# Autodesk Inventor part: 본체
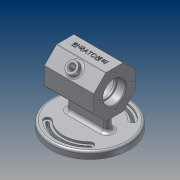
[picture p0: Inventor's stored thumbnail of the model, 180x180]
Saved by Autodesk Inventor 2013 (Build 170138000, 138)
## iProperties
Created: 2017-06
Part Number: 본체
Material: 알루미늄 6061
Document SubType Name: Modeling
Designer: Windows7
Density: 2.71 g/cm^3
Mass: 562.523 g
Surface Area: 565.555 cm^2
Volume: 207.573 cm^3
Author: Windows7
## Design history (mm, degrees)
sketch "스케치1" dims "d0" = 60
  geometry: L1 (12.426, 30)-(30, 12.426); L2 (30, 12.426)-(30, -12.426); L3 (30, -12.426)-(12.426, -30); L4 (12.426, -30)-(-12.426, -30); L5 (-12.426, -30)-(-30, -12.426); L6 (-30, -12.426)-(-30, 12.426); L7 (-30, 12.426)-(-12.426, 30); L8 (-12.426, 30)-(12.426, 30); 4 further points
  constraints: 16 end point, 2 coincident, 2 vertical alignment, 1 midpoint, 19 other
extrude "돌출1" new body sketch "스케치1" stored distance "d1" = 70; taper "d2" = 0 deg
sketch "스케치2"
  geometry: C1 r 25 at (0, 0); 1 further point
  constraints: 1 centre point, 1 coincident
  dimensions: "d3" = 50 diameter of C1
extrude "돌출2" cut sketch "스케치2" stored distance "d4" = 40; taper "d5" = 0 deg
sketch "스케치3"
  geometry: 1 further point
hole "구멍1" sketch "스케치3" at (0, 0) diameter "d6" = 28; stored, may be unused: countersink angle "d10" = 90 deg, drill point angle "d12" = 0 deg; dims "d7" = 6, "d8" = 32, "d9" = 12, "d11" = 15
chamfer "모따기1" distance "d13" = 1; stored, may be unused: second distance "d14" = 2, angle "d15" = 45 deg
node "작업 평면1"
sketch "스케치4"
  geometry: C1 r 55 at (0, 0); 1 further point
  constraints: 1 centre point, 1 coincident
  dimensions: "d17" = 110 diameter of C1
extrude "돌출3" join sketch "스케치4" distance "d18" = 10; taper "d19" = 0 deg
sketch "스케치5" dims "d20" = 86
  geometry: L1 (0, 55)-(0, -55); L2 (0, 0)-(-38.891, 38.891); A1 r 55 centre (0, 0) between (0, 55) and (0, -55) reference; A2 r 48 centre (0, 0) between (33.941, 33.941) and (-33.941, 33.941); A3 r 38 centre (0, 0) between (26.87, 26.87) and (-26.87, 26.87); A4 r 5 centre (-30.406, 30.406) between (-33.941, 33.941) and (-26.87, 26.87); A5 r 5 centre (30.406, 30.406) between (26.87, 26.87) and (33.941, 33.941)
  constraints: 11 point on circle, 4 centre point, 4 end point, 2 coincident, 1 midpoint, 1 point on line, 1 symmetric about line, 1 tangent, 1 vertical, 4 other
  dimensions: "d21" = 45 deg angle of L1 L2; "d23" = 96 diameter of A2; "d24" = 76 diameter of A3
extrude "돌출4" cut sketch "스케치5" distance "d25" = 3; taper "d26" = 0 deg
sketch "스케치6"
  geometry: A1 r 5 centre (-30.406, 30.406) between (-33.941, 33.941) and (-26.87, 26.87) reference; A2 r 38 centre (0, 0) between (26.87, 26.87) and (-26.87, 26.87) reference; A3 r 5 centre (30.406, 30.406) between (26.87, 26.87) and (33.941, 33.941) reference; A4 r 48 centre (0, 0) between (33.941, 33.941) and (-33.941, 33.941) reference; A5 r 2 centre (-30.406, 30.406) between (-31.82, 31.82) and (-28.991, 28.991); A6 r 41 centre (0, 0) between (28.991, 28.991) and (-28.991, 28.991); A7 r 2 centre (30.406, 30.406) between (28.991, 28.991) and (31.82, 31.82); A8 r 45 centre (0, 0) between (31.82, 31.82) and (-31.82, 31.82)
  constraints: 8 point on circle, 4 centre point, 3 other
  dimensions: "d27" = 3 radial gap between concentric circles of A8 A4
extrude "돌출5" cut sketch "스케치6" stored distance "d28" = 3; taper "d29" = 0 deg
sketch "스케치8"
  geometry: L1 (-24, -5)-(24, -5); L2 (24, -5)-(24, 5); L3 (24, 5)-(-24, 5); L4 (-24, 5)-(-24, -5); L5 (-24, -5)-(24, 5); L6 (24, -5)-(-24, 5); A1 r 38 centre (0, 0) between (-26.87, -26.87) and (26.87, -26.87) reference; 4 further points
  constraints: 12 end point, 5 midpoint, 2 parallel, 2 vertical alignment, 1 coincident, 1 horizontal, 1 perpendicular, 4 other
  dimensions: "d30" = 48 distance of L2.end L3.end; "d32" = 10 distance of L1.end L2.end
extrude "돌출6" join sketch "스케치8" stored distance "d33" = 3; taper "d34" = 0 deg
sketch "스케치9"
  geometry: L1 (70, 42.426)-(0, 42.426) reference; L2 (0, 24.853)-(0, 42.426) reference; 2 further points
  constraints: 1 other
  dimensions: "d36" = 30 distance from line of L1 point (35, 12.426); "d73" = 35 distance from line of point (35, 12.426) L2
feature "엠보싱1" sketch "스케치9" dims "d37" = 0.5, "d38" = 0
sketch "스케치10"
  geometry: L1 (30, 12.426)-(12.426, 30) reference; L2 (12.426, 30)-(-12.426, 30) reference; L3 (-12.426, 30)-(-30, 12.426) reference; L4 (-30, 12.426)-(-30, -12.426) reference; L5 (-30, -12.426)-(-12.426, -30) reference; L6 (-12.426, -30)-(12.426, -30) reference; L7 (12.426, -30)-(30, -12.426) reference; L8 (30, -12.426)-(30, 12.426) reference; L9 (30, 0)-(-30, 0); L10 (0, 0)-(26.163, 26.163); C1 r 17 at (0, 0) reference; 1 further point
  constraints: 5 end point, 3 midpoint
  dimensions: "d42" = 45 deg angle of L10 L9; "d43" = 7 distance from line of L10.end L1
  node "투영된 루프1"
node "작업 평면2"
sketch "스케치11"
  geometry: C1 r 8 at (0, 0); 1 further point
  constraints: 1 centre point, 1 coincident
  dimensions: "d44" = 16 diameter of C1
extrude "돌출7" join sketch "스케치11" stored distance "d45" = 3; taper "d46" = 0 deg
sketch "스케치12"
  geometry: C1 r 8 at (0, 0) reference
hole "구멍2" sketch "스케치12" at (0, 0) diameter "d47" = 8; stored, may be unused: countersink angle "d51" = 90 deg, drill point angle "d53" = 0 deg; dims "d48" = 6, "d49" = 32, "d50" = 12, "d52" = 15
fillet "모깎기1" dims "d54" = 3
chamfer "모따기2" distance "d55" = 1; stored, may be unused: second distance "d56" = 2, angle "d57" = 45 deg
fillet "모깎기2" dims "d58" = 1
fillet "모깎기3" dims "d59" = 0.3
fillet "모깎기4" dims "d60" = 3
sketch "스케치13"
  geometry: C1 r 17 at (0, 0) reference; 1 further point
  constraints: 1 vertical alignment
  dimensions: "d62" = 23 distance of C1.centre point (0, 23)
hole "구멍3" sketch "스케치13" at (0, 23) diameter "d63" = 3.242; stored, may be unused: countersink angle "d67" = 90 deg, drill point angle "d69" = 118 deg; dims "d64" = 8, "d65" = 32, "d66" = 12, "d68" = 10
fillet "모깎기6" dims "d74" = 5
fillet "모깎기7" dims "d75" = 3
node "솔리드1"
mirror "대칭1"
mirror "대칭2"
pattern_circular "원형 패턴1" dims angle "d71" = 360 deg
mirror "대칭3"
other parameters: "d16" = -62
